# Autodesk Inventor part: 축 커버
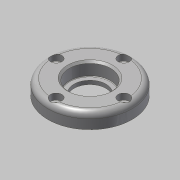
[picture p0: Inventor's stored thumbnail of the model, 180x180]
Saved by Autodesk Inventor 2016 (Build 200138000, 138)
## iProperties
Created: 2015-10
Part Number: 축 커버
Document SubType Name: Modeling
Designer: mdu
Density: 7.86 g/cm^3
Material: 강철, 연강
Mass: 76.1259 g
Surface Area: 48.0703 cm^2
Volume: 9.68523 cm^3
Appearance: Steel
Author: mdu
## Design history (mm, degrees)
sketch "스케치1"
  geometry: C1 r 22.355 at (0, 0) reference; C2 r 14 at (0, 0) reference; C3 r 1.23 at (0, 18) reference; 1 further point
extrude "돌출1" new body sketch "스케치1" distance "d0" = 8; taper "d1" = 0 deg
sketch "스케치2"
  geometry: C1 r 14 at (0, 0) reference; 1 further point
extrude "돌출2" join sketch "스케치2" distance "d2" = 3; taper "d3" = 0 deg
hole "구멍1" diameter "d6" = 17; stored, may be unused: countersink angle "d10" = 90 deg, drill point angle "d12" = 118 deg; dims "d4" = 10, "d5" = 10, "d7" = 6, "d8" = 23, "d9" = 2, "d11" = 8
hole "구멍2" diameter "d15" = 22; stored, may be unused: countersink angle "d19" = 90 deg, drill point angle "d21" = 0 deg; dims "d13" = 10, "d14" = 10, "d16" = 6, "d17" = 25, "d18" = 2, "d20" = 7
fillet "모깎기1" dims "d22" = 3, "d23" = 0.3
chamfer "모따기1" distance "d24" = 1; stored, may be unused: second distance "d25" = 2, angle "d26" = 45 deg
sketch "스케치3"
  geometry: 2 further points
hole "구멍3" sketch "스케치3" at (0, 18) diameter "d27" = 3.4; stored, may be unused: countersink angle "d31" = 90 deg, drill point angle "d33" = 118 deg; dims "d28" = 6, "d29" = 6, "d30" = 3.3, "d32" = 7
node "솔리드1"
pattern_circular "원형 패턴1" dims angle "d35" = 360 deg
node "참조1"
node "참조2"
node "참조3"
